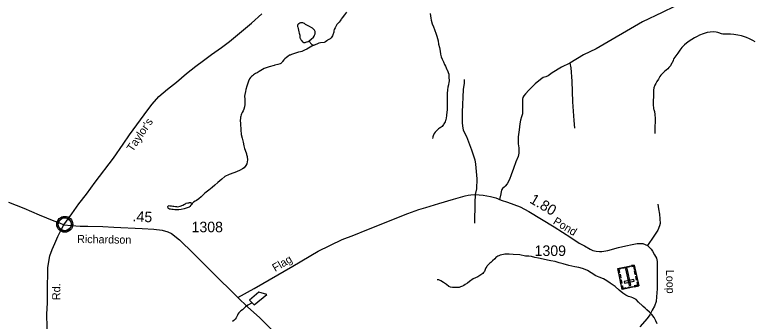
# Model space of a CAD drawing. Extents: x 2220236 to 2384410, y 720751 to 894131.
# Drawn here: x 2267338 to 2276098, y 824550 to 828191 of the extents above; entities that cross this region are included whole.
import ezdxf

# ---------------------------------------------------------------- set-up
doc = ezdxf.new("R2010")
doc.units = 0
for name, color, linetype in [('Exist Civil Demographics Community CELL', 7, 'Continuous'), ('Exist Cultural Cemetery CELL', 7, 'Continuous'), ('Exist Hydrographic Misc Water Feature', 7, 'Continuous'), ('Exist Hydrographic Pond Under 1500 Sq Ft', 7, 'Continuous'), ('Exist Road Non-System Type 51', 7, 'Continuous'), ('Exist Road Secondary Mileage Hundredths English Label', 7, 'Continuous'), ('Exist Road Secondary Type 51 Attributed', 7, 'Continuous'), ('Exist Road Secondary Type 51 Label', 7, 'Continuous'), ('Exist Road Secondary Type 51 Number Label', 7, 'Continuous')]:
    doc.layers.add(name, color=color, linetype=linetype)

msp = doc.modelspace()

# ---------------------------------------------------------------- linework, layer by layer
at = {"layer": 'Exist Civil Demographics Community CELL'}
msp.add_lwpolyline([(2267853.2, 825714.7), (2267854.1, 825720.2), (2267855.9, 825726.8), (2267858.8, 825734), (2267861.8, 825739.8), (2267865.1, 825745.5), (2267868.9, 825750.6), (2267872.8, 825755), (2267877.4, 825759.6), (2267882.9, 825764.2), (2267888.4, 825767.8), (2267893.3, 825770.7), (2267898.3, 825773.1), (2267903.8, 825775.4), (2267909.4, 825777.3), (2267913.7, 825778.4), (2267918.6, 825779.1), (2267922.7, 825779.9), (2267929.1, 825780.1), (2267933.5, 825780), (2267939.2, 825779.8), (2267944.1, 825779), (2267949, 825778), (2267954, 825776.6), (2267959.2, 825774.7), (2267965.8, 825771.8), (2267972.1, 825768.3), (2267977.1, 825764.7), (2267982.3, 825760.7), (2267985.6, 825757.6), (2267989.7, 825753.2), (2267993.6, 825748.5), (2267996.7, 825743.9), (2267999.8, 825738.9), (2268002.3, 825733.7), (2268004.3, 825728.7), (2268005.9, 825723.7), (2268007.1, 825719.1), (2268008.2, 825713.1), (2268008.9, 825708.4), (2268009.1, 825702.4), (2268008.9, 825696.6), (2268008.4, 825690.9), (2268007.4, 825685.4), (2268005.8, 825679.3), (2268003.9, 825673.4), (2268001.6, 825668.4), (2267998.4, 825662.4), (2267995.2, 825657), (2267991.7, 825652.4), (2267987.5, 825647.6), (2267982.2, 825642.6), (2267977.2, 825638.5), (2267972.2, 825635.1), (2267967.8, 825632.6), (2267961, 825629.3), (2267953.9, 825626.6), (2267947.9, 825625.2), (2267941.3, 825623.9), (2267936.9, 825623.4), (2267932.4, 825623.1), (2267926.8, 825623.1), (2267922.5, 825623.5), (2267916.9, 825624.3), (2267911, 825625.6), (2267906.4, 825626.9), (2267901.2, 825628.8), (2267896.6, 825630.7), (2267892.7, 825633), (2267885.9, 825637.1), (2267880.3, 825641.3), (2267875.4, 825645.8), (2267871, 825650.7), (2267867.8, 825654.6), (2267864.8, 825658.8), (2267860.7, 825665.9), (2267859, 825669.5), (2267857.3, 825673.5), (2267854.7, 825681.7), (2267853.2, 825688.7), (2267852.5, 825693.9), (2267852.1, 825700.2), (2267852.1, 825704.9), (2267852.6, 825711.4)], close=True, dxfattribs=at)
for centre, radius in [((2267930.8, 825702.2), 94.3), ((2267930.5, 825702.5), 76.7)]:
    msp.add_circle(centre, radius, dxfattribs=at)
at = {"layer": 'Exist Cultural Cemetery CELL'}
for points in [[(2274738.9, 824969.3), (2274544.1, 824927.9), (2274491.2, 825177), (2274686, 825218.3)], [(2274523.6, 825183.9), (2274526, 825172.6), (2274504.5, 825168.1), (2274512.9, 825128.5), (2274502, 825126.2), (2274491.2, 825177)], [(2274632.2, 825195.2), (2274549.2, 825177.6), (2274546.8, 825188.7), (2274629.8, 825206.3)], [(2274626.1, 824975.3), (2274644.4, 824979.2), (2274602.3, 825177.5), (2274584, 825173.6)], [(2274653.6, 825211.4), (2274656, 825200.2), (2274677.5, 825204.8), (2274685.9, 825165.2), (2274696.8, 825167.5), (2274686, 825218.3)], [(2274700.5, 825149.9), (2274709.5, 825107.6), (2274698.4, 825105.2), (2274689.4, 825147.6)], [(2274517.4, 825108.7), (2274526.4, 825066.3), (2274515.2, 825063.9), (2274506.2, 825106.3)], [(2274714.5, 825084.2), (2274723.5, 825041.8), (2274712.3, 825039.4), (2274703.4, 825081.8)], [(2274531, 825044.2), (2274540, 825001.8), (2274528.9, 824999.4), (2274519.9, 825041.8)], [(2274535, 824970.3), (2274546.1, 824972.7), (2274552.8, 824941.2), (2274592.5, 824949.6), (2274594.8, 824938.7), (2274544.1, 824927.9)], [(2274684.8, 825027.4), (2274680.9, 825045.6), (2274565.8, 825021.2), (2274569.6, 825002.9)], [(2274729.9, 825011.6), (2274718.8, 825009.3), (2274725.5, 824977.8), (2274685.8, 824969.4), (2274688.1, 824958.5), (2274738.9, 824969.3)], [(2274666.4, 824953.9), (2274615.7, 824943.1), (2274613.3, 824954.3), (2274664, 824965)]]:
    msp.add_lwpolyline(points, close=True, dxfattribs=at)
at = {"layer": 'Exist Hydrographic Misc Water Feature'}
for points in [[(2271273.1, 828219.9), (2271249.2, 828190.2), (2271221.6, 828153.7), (2271210.1, 828137.5), (2271206, 828131.1), (2271198.2, 828119.1), (2271186, 828101.3), (2271170.3, 828086.9), (2271158.3, 828074.7), (2271144.7, 828053), (2271136.8, 828036.7), (2271127.2, 828014.6), (2271123, 828000.9), (2271121.3, 827984.6), (2271117.4, 827970.5), (2271113.3, 827962.4), (2271105.6, 827940.6), (2271097.8, 827926.7), (2271090, 827914.7), (2271078, 827904.1), (2271064.1, 827897.8), (2271046.2, 827887.7), (2271040.5, 827881.9), (2271022.4, 827867.5), (2271014.5, 827863.8), (2271006.2, 827861.3), (2270965.5, 827857.2), (2270945.4, 827852.1), (2270930.5, 827846.5), (2270900.7, 827835), (2270889.8, 827829.3)], [(2272264.7, 828205.2), (2272273.1, 828150.9), (2272277.5, 828126.9), (2272289.7, 828083.4), (2272304, 828047.6), (2272318.4, 828013.9), (2272336.7, 827959.4), (2272345, 827935.3), (2272359.6, 827880.2), (2272366, 827839.7), (2272376.4, 827801.8), (2272383, 827758.3), (2272389.1, 827720.5), (2272397.3, 827689.8), (2272407.6, 827664.4), (2272421.7, 827632.9), (2272436.1, 827598.8), (2272446.6, 827580.6), (2272464.8, 827540.8), (2272468.9, 827535.2), (2272485.2, 827483), (2272485.2, 827466.6), (2272487.6, 827441.3), (2272490, 827415), (2272490, 827399.3), (2272488.2, 827391.1), (2272482.3, 827359.4), (2272476.8, 827329), (2272470.9, 827299), (2272467.4, 827257.1), (2272465.6, 827217.1), (2272468, 827193.1), (2272468.4, 827146.5), (2272466.7, 827112.8), (2272467.1, 827068.5), (2272463.3, 827026.9), (2272459.6, 827004.7), (2272457.9, 826988.3), (2272449.4, 826943.5), (2272446.3, 826932.8), (2272441.4, 826919.8), (2272434.6, 826906.8), (2272429.4, 826895.4), (2272423.3, 826886.7), (2272416.9, 826876), (2272406.8, 826864.1), (2272395.1, 826854.5), (2272385.1, 826848.1), (2272375.2, 826841.8), (2272365.2, 826836.1), (2272349.2, 826821.6), (2272331.4, 826805.6), (2272323.7, 826795.3), (2272313.5, 826779.1), (2272310.1, 826771.6), (2272301.8, 826753.1), (2272298, 826741.7), (2272296.2, 826735.2), (2272292.3, 826721.1)], [(2276122.1, 827867.8), (2276091.9, 827885.5), (2276053.7, 827905.3), (2276017.6, 827920.8), (2275957.3, 827940.8), (2275915.5, 827948.2), (2275869.4, 827955.7), (2275829.4, 827959.2), (2275803.2, 827961.4), (2275777.3, 827958.6), (2275759.2, 827959), (2275737.3, 827960.1), (2275723.3, 827964.7), (2275709.3, 827968.2), (2275703.4, 827970), (2275677.4, 827980.4), (2275657.1, 827984.1), (2275621.1, 827987.1), (2275585.6, 827985.6), (2275551.1, 827980.4), (2275505.2, 827965.9), (2275461.8, 827947.1), (2275433.7, 827933.6), (2275399.9, 827915.6), (2275368.3, 827897.2), (2275326.4, 827868.6), (2275280.8, 827834.4), (2275250.9, 827802.3), (2275225.3, 827770), (2275209.7, 827745.7), (2275201.6, 827733.4), (2275166.5, 827684.9), (2275156.3, 827671.4), (2275152.6, 827663.3), (2275146.3, 827647), (2275134.6, 827621), (2275128.9, 827611.3), (2275115.2, 827585.3), (2275097.3, 827562.7), (2275083.3, 827548.2), (2275043.6, 827517.9), (2275027.9, 827501.8), (2275002, 827473.5), (2274990.2, 827455.7), (2274972.9, 827427.5), (2274954.9, 827397.4), (2274941, 827375.7), (2274931.3, 827354.6), (2274919.5, 827321.1), (2274915.6, 827293.3), (2274913.9, 827258.9), (2274914.2, 827240.8), (2274914.6, 827211.3), (2274911.6, 827177.9), (2274911.2, 827158.9), (2274911.2, 827157.2), (2274911.3, 827131), (2274911.6, 827112.3), (2274913.7, 827090.9), (2274916.7, 827075.1), (2274919.8, 827065.2), (2274926.2, 827043.1), (2274930.4, 827006.9), (2274935, 826959.3), (2274933.1, 826919), (2274932, 826863.2), (2274930.1, 826820.6), (2274930.1, 826805.2), (2274930.6, 826781.3)], [(2270830.2, 827879.7), (2270838.7, 827865.8), (2270840.6, 827862.5), (2270846.7, 827854.1), (2270852.4, 827846.5), (2270862.8, 827838.1), (2270872.9, 827834.6), (2270889.8, 827829.3)], [(2270889.8, 827829.3), (2270861, 827816.1), (2270821.1, 827792.3), (2270803.5, 827781.9), (2270775.4, 827769.3), (2270757.5, 827761.5), (2270743.6, 827755.2), (2270725.8, 827749.1), (2270705.4, 827744.6), (2270681.6, 827738.5), (2270621.8, 827718.4), (2270604.3, 827712.2), (2270598, 827710), (2270576.1, 827695.7), (2270559.8, 827683), (2270542.4, 827667.6), (2270530.7, 827655.7), (2270514.8, 827635.3), (2270509.1, 827627.3), (2270500.7, 827619.2), (2270492.4, 827612.2), (2270485.1, 827609.1), (2270459.3, 827600.4), (2270423, 827590.7), (2270415.1, 827588.2), (2270357.4, 827571.4), (2270319.4, 827561.7), (2270295.7, 827553), (2270275.4, 827541.2), (2270255.8, 827528.5), (2270237.8, 827516.4), (2270212.2, 827500.6), (2270194, 827492.1), (2270180.4, 827484.2), (2270168.4, 827476.2), (2270156.4, 827465.6), (2270144.7, 827455.4), (2270134.7, 827445.8), (2270122.9, 827429.6), (2270111.2, 827403.6), (2270097.3, 827365.2), (2270089.6, 827343.4), (2270080.2, 827303.2), (2270075.5, 827279.7), (2270066.6, 827244.5), (2270064.5, 827223.2), (2270065, 827187.1), (2270067, 827170.7), (2270067.3, 827152.6), (2270067.7, 827141.1), (2270067.7, 827125.7), (2270063.5, 827098.6), (2270056.1, 827070.8), (2270048.1, 827050.7), (2270036.5, 827030.3), (2270028.6, 827012.4), (2270024.8, 827002.6), (2270020.9, 826986.3), (2270017, 826972.6), (2270015.1, 826960.2), (2270013.3, 826938.2), (2270013.7, 826894.6), (2270018.5, 826822.3), (2270024.9, 826768.1), (2270035.5, 826724.6), (2270045.6, 826678.5), (2270056.2, 826633), (2270064.4, 826601), (2270081.1, 826551.4), (2270084.7, 826538.9), (2270087.2, 826529), (2270091.2, 826517.4), (2270093.3, 826506.9), (2270095.6, 826493.7), (2270097.2, 826477.3), (2270097.3, 826465.8), (2270095.9, 826445.2), (2270090.2, 826420.7), (2270080.2, 826398.9), (2270060.6, 826373.1), (2270041, 826358.8), (2270012.8, 826344.6), (2269968.8, 826325.8), (2269935.1, 826314), (2269879.6, 826293.2), (2269829.5, 826268.7), (2269795.8, 826238.2), (2269748.1, 826199.8), (2269712.7, 826167.8), (2269680.9, 826139.9), (2269638.9, 826107), (2269591.6, 826070.2), (2269548, 826026.2), (2269522, 826006.1), (2269494.3, 825983.7), (2269476.5, 825975.9), (2269458.5, 825963.1)], [(2269458.5, 825963.1), (2269446.5, 825953.5), (2269440.4, 825947.1)], [(2274070.9, 825178.8), (2274030.7, 825188.8), (2273983, 825196.4), (2273910.8, 825211.6), (2273842.7, 825231.1), (2273794.8, 825244.5), (2273748.5, 825260.2), (2273698.5, 825269.5), (2273658.3, 825276.9), (2273604.1, 825286.9), (2273552.2, 825300.4), (2273508.1, 825309.5), (2273467.7, 825319.2), (2273435.9, 825323.1), (2273397.9, 825324.9), (2273327.7, 825337.8), (2273248.1, 825345.1), (2273201.9, 825345.4), (2273169.8, 825346.7), (2273149.7, 825346.4), (2273135.9, 825344.1), (2273115.8, 825338), (2273096, 825334.4), (2273080.2, 825328.2), (2273068.2, 825321.9), (2273044.3, 825306), (2273030.6, 825293.2), (2273006.4, 825269.1), (2272984.7, 825248.8), (2272975, 825239.2), (2272955.3, 825220.9), (2272941.3, 825210.4), (2272937.2, 825202.3), (2272927.3, 825186.1), (2272923.5, 825176.3), (2272915.8, 825154.5), (2272909.7, 825140.5), (2272899.9, 825130.2), (2272890.2, 825118), (2272866.2, 825102.1), (2272830.6, 825077.5), (2272775, 825053.1), (2272733.1, 825024.5), (2272707.1, 825004.7), (2272679.2, 824987.9), (2272663.5, 824976), (2272655.5, 824969.6), (2272647.6, 824965.6), (2272635.7, 824961.9), (2272623.5, 824957.9), (2272609.6, 824953.2), (2272585.9, 824949.8), (2272558, 824949.4), (2272529.8, 824950.9), (2272508, 824956.3), (2272487.5, 824964.9), (2272459.7, 824985.8), (2272425.5, 825012.1), (2272391.1, 825031.5), (2272367.1, 825041.2), (2272347.1, 825043.3)], [(2274958.5, 824518.5), (2274942.3, 824556.6), (2274923.7, 824596.3), (2274895.6, 824632), (2274869.3, 824659.8), (2274837, 824685.7), (2274814.8, 824707.5), (2274792.6, 824725.3), (2274782.6, 824735.4), (2274738.6, 824778.9), (2274708, 824808.1), (2274685.7, 824822.6), (2274670.1, 824827.9), (2274647.9, 824835.6), (2274617.6, 824846), (2274587.8, 824861.4), (2274551.5, 824885.1), (2274507, 824920.5), (2274458.7, 824962.5), (2274402.5, 825004), (2274362, 825031.7), (2274319.8, 825053.3), (2274269.8, 825074.6), (2274231.8, 825091.8), (2274173.4, 825123.5), (2274131.3, 825151.3), (2274103.1, 825166.6), (2274070.9, 825178.8)], [(2270153, 824768.9), (2270103.3, 824742.7), (2270075.7, 824723), (2270037.9, 824686.7), (2270018.2, 824672.3), (2269996.4, 824649.8), (2269984.6, 824633.7), (2269978.5, 824624), (2269974.7, 824615.8), (2269966.8, 824598), (2269962.7, 824589.8), (2269950.9, 824575.3), (2269935.1, 824557.6), (2269919.2, 824547.4)]]:
    msp.add_lwpolyline(points, dxfattribs=at)
at = {"layer": 'Exist Hydrographic Pond Under 1500 Sq Ft'}
for points in [[(2270830.2, 827879.7), (2270854.5, 827900.5), (2270880.6, 827924.6), (2270887.7, 827934.3), (2270893.5, 827946.6), (2270898, 827957), (2270899.8, 827963.6), (2270900.9, 827969.4), (2270902.6, 827974.3), (2270902.5, 827984.2), (2270901.4, 827992.4), (2270895.1, 828006.3), (2270887.1, 828016.3), (2270867.7, 828029.8), (2270826.9, 828053.6), (2270786.7, 828075.8), (2270772.8, 828085.3), (2270764, 828091), (2270756.5, 828092.8), (2270748.4, 828095.6), (2270738.5, 828094.8), (2270726.3, 828092.8), (2270718.7, 828088.7), (2270706.4, 828082.4), (2270700.5, 828078.6), (2270694.1, 828072.1), (2270692.4, 828068.9), (2270692.9, 828063), (2270692.7, 828052.5), (2270694.8, 828042.6), (2270697.8, 828026.8), (2270702.3, 828008), (2270705.5, 827988.9), (2270709.7, 827970.8), (2270713.8, 827960.9), (2270717.7, 827947), (2270719.9, 827938.8), (2270720.4, 827930.5), (2270720.2, 827923), (2270720.1, 827917.4), (2270722, 827913.1), (2270726, 827903.2), (2270730.4, 827894.9), (2270736.2, 827887.6), (2270742.3, 827880.9), (2270752.5, 827869.2), (2270756.8, 827867.5), (2270764.5, 827863), (2270772.7, 827861.2), (2270776.6, 827861.2), (2270782.3, 827862.7), (2270791.8, 827865.8), (2270800.4, 827868.2), (2270806.3, 827869.7), (2270816.6, 827874.4), (2270830.2, 827879.7)], [(2269440.4, 825947.1), (2269433, 825937.4), (2269427, 825929.3), (2269415.2, 825914.8), (2269405.2, 825906.8), (2269383, 825898.4), (2269347.7, 825886.7), (2269311.4, 825876), (2269284.7, 825873.2), (2269253.3, 825873.2), (2269235.3, 825875.2), (2269215.3, 825877.3), (2269199.3, 825879.3), (2269183.2, 825881.2), (2269173.1, 825882.1), (2269161.4, 825888.9), (2269157.3, 825894.9), (2269155, 825910.4), (2269155.1, 825914.6), (2269157.1, 825918.5), (2269163.1, 825922.7), (2269167.7, 825923.2), (2269175.2, 825923.1), (2269187, 825921.2), (2269198.1, 825919.3), (2269212.5, 825916.7), (2269223.3, 825915.5), (2269244.2, 825912.8), (2269253.1, 825911.6), (2269257, 825911.5), (2269267.5, 825911.3), (2269284.9, 825913.6), (2269301.1, 825918.2), (2269330.8, 825928), (2269352.7, 825940.7), (2269364.7, 825946.4), (2269372.6, 825951.1), (2269390.4, 825956.3), (2269400.7, 825958.7), (2269408.6, 825960.9), (2269420.4, 825960.6), (2269430.8, 825957.1), (2269440.4, 825947.1)], [(2270153, 824768.9), (2270177.4, 824743.8), (2270326, 824867), (2270233.7, 824894.2), (2270120.9, 824801.4), (2270153, 824768.9)]]:
    msp.add_lwpolyline(points, dxfattribs=at)
at = {"layer": 'Exist Road Non-System Type 51'}
for points in [[(2275993.4, 828726.2), (2275660.9, 828558.9), (2275310.7, 828358.1), (2275019.5, 828218.3), (2274785.4, 828106.1), (2274234.5, 827785.2), (2274085, 827714.3), (2273923.7, 827615.9)], [(2273923.7, 827615.9), (2273825.3, 827568.7), (2273713.2, 827501.7), (2273664, 827466.3), (2273638.4, 827454.5), (2273604.9, 827444.6), (2273573.5, 827423), (2273510.5, 827369.8), (2273435.7, 827295), (2273394.4, 827249.7), (2273374.8, 827228.1), (2273363, 827208.4), (2273361, 827186.7), (2273361, 827104), (2273361, 827015.5), (2273349.2, 826978.1), (2273337.4, 826936.7), (2273327.5, 826895.4), (2273319.7, 826824.5), (2273309.8, 826739.8), (2273309.8, 826657.2), (2273315.7, 826609.9), (2273317.7, 826568.6), (2273315.7, 826544.9), (2273307.9, 826507.5), (2273282.3, 826442.6), (2273252.8, 826365.8), (2273227.2, 826291), (2273207.5, 826233.9), (2273178, 826180.7), (2273156.4, 826153.2), (2273144.6, 826141.4), (2273124.9, 826125.6), (2273113.1, 826107.9), (2273109.2, 826092.1), (2273103.3, 826062.6), (2273087.5, 825997.7)], [(2273923.7, 827615.9), (2273935.5, 827560.8), (2273945.3, 827401.3), (2273953.2, 827157.2), (2273970.9, 826934.7), (2273976.8, 826844.2)], [(2272668.9, 827422.7), (2272667.4, 827378.7), (2272658, 827302.7), (2272646.7, 827034.6), (2272645.9, 826910.7), (2272648.2, 826868.6), (2272658.5, 826824.8), (2272672.9, 826787), (2272695.4, 826743.3), (2272754.7, 826585.9), (2272783.6, 826504.1), (2272793.8, 826466.3), (2272804.4, 826416.3), (2272820.9, 826241.8), (2272815, 826121.7), (2272797.3, 826054.7)], [(2272797.3, 826054.7), (2272793.4, 825956.3), (2272790.4, 825714.2)], [(2274965.9, 825942.9), (2274972.3, 825887), (2274987.1, 825823.1), (2274994, 825713.2), (2274986.3, 825683.2), (2274967.4, 825633.4), (2274918.2, 825562.6), (2274844.6, 825450)]]:
    msp.add_lwpolyline(points, dxfattribs=at)
at = {"layer": 'Exist Road Secondary Type 51 Attributed'}
for points in [[(2267921.3, 825696.7), (2268016, 825825.7), (2268096.8, 825944.4), (2268189.6, 826061.2), (2268292.3, 826202.1), (2268509.9, 826485.6), (2268624, 826653.1), (2268698.9, 826763.7), (2268918, 827061.7), (2268967.4, 827128), (2269048.5, 827220.7), (2269147.7, 827307.6), (2269256.8, 827390.6), (2269372.9, 827492.4), (2269487.1, 827578.4), (2269576.6, 827648.7), (2269669.7, 827717.3), (2269791.7, 827803.4), (2269883, 827871.9), (2270147.3, 828091.5), (2270266.7, 828201.8)], [(2269984.9, 824832.2), (2270177.4, 824938.2), (2270636.8, 825204.4), (2270937, 825381.3), (2271221.4, 825519.8), (2271360.8, 825573.1), (2271512.3, 825634.5), (2271998.5, 825828.3), (2272130.4, 825877.6), (2272215, 825903.2), (2272369, 825948.5), (2272540.4, 826002.1), (2272682, 826039.3), (2272717.1, 826046.3), (2272749.1, 826050.8), (2272797.3, 826054.7), (2272893.9, 826047.3), (2272981.3, 826033.1), (2273044.2, 826015.4), (2273109.2, 825989.8), (2273182, 825964.2), (2273333.4, 825909.1), (2273436.7, 825853.9), (2273737.7, 825672.8), (2273934.1, 825543.3), (2274034.7, 825476.4), (2274094.9, 825445), (2274165.2, 825405.5), (2274196.2, 825391.3), (2274233.5, 825382.3), (2274272.9, 825377.5), (2274302.4, 825379.5), (2274371.3, 825391.3), (2274499.1, 825424.8), (2274587.7, 825446.4), (2274660.5, 825460.2), (2274721.5, 825474), (2274788.3, 825472), (2274844.6, 825450), (2274886.9, 825408.3), (2274902.5, 825383.4), (2274928, 825340.1), (2274949.7, 825298.8), (2274959.5, 825259.4), (2274957.3, 824937.3), (2274952.3, 824839.4), (2274944.6, 824785.3), (2274925.1, 824731.1), (2274897.8, 824680.9), (2274872.3, 824628.6), (2274840.8, 824584.4), (2274751.7, 824485.5)], [(2267263.1, 825964.5), (2267443.6, 825894.2), (2267628.2, 825813.9), (2267800.9, 825743.6), (2267869, 825720.4), (2267921.3, 825696.7)], [(2267318.1, 823454.1), (2267503, 823735.7), (2267564, 823840), (2267640.7, 823977.8), (2267682.7, 824073.3), (2267693.6, 824124.5), (2267713, 824251.5), (2267718.2, 824331.5), (2267720.8, 824477.4), (2267719.3, 824633.4), (2267725.3, 824769.2), (2267727.3, 824901.1), (2267730.2, 825186.6), (2267740.1, 825259.4), (2267753.9, 825326.3), (2267781.4, 825401.1), (2267810.9, 825474), (2267848.3, 825558.6), (2267879.9, 825620.4), (2267921.3, 825696.7)], [(2267921.3, 825696.7), (2268009.6, 825686.6), (2268060.8, 825684.6), (2268113.3, 825678.5), (2268204.4, 825680.7), (2268381.5, 825674.8), (2268511.3, 825666.2), (2268847.7, 825653.1), (2268987.3, 825642.8), (2269084.8, 825631.5), (2269151.7, 825611.8), (2269195, 825594.1), (2269291.4, 825519.3), (2269456.6, 825355.9), (2269675, 825135.4), (2269984.9, 824832.2)], [(2269984.9, 824832.2), (2270099, 824722), (2270246.6, 824590.1), (2270400, 824436.5), (2270563.3, 824279), (2270738.4, 824095.9), (2270923.4, 823901), (2271076.8, 823741.6), (2271288.3, 823525), (2271428, 823379.3), (2271581.5, 823231.7), (2271702.5, 823131.3), (2271868, 823013.8)]]:
    msp.add_lwpolyline(points, dxfattribs=at)

# ---------------------------------------------------------------- texts
at = {"layer": 'Exist Road Secondary Mileage Hundredths English Label'}
for s, rotation, p in [('1.80', 329.45085, (2273435.2, 825964.3)), ('.45', 356.60992, (2268732.8, 825737.6))]:
    msp.add_text(s, height=125, rotation=rotation, dxfattribs=at).set_placement(p)
at = {"layer": 'Exist Road Secondary Type 51 Label'}
for s, rotation, p in [("Taylor's", 55.89425, (2268735.6, 826557.2)), ('Pond', 329.07103, (2273715.3, 825712.7)), ('Richardson', 359.07018, (2268076.7, 825480.8)), ('Flag', 30.50966, (2270426.3, 825135.3)), ('Loop', 271.91519, (2275063.2, 825159.8)), ('Rd.', 89.58724, (2267876.4, 824801.7))]:
    msp.add_text(s, height=95, rotation=rotation, dxfattribs=at).set_placement(p)
at = {"layer": 'Exist Road Secondary Type 51 Number Label'}
for s, p in [('1308', (2269435.1, 825607.6)), ('1309', (2273504.5, 825325.9))]:
    msp.add_text(s, height=125, dxfattribs=at).set_placement(p)

doc.saveas('drawing.dxf')
